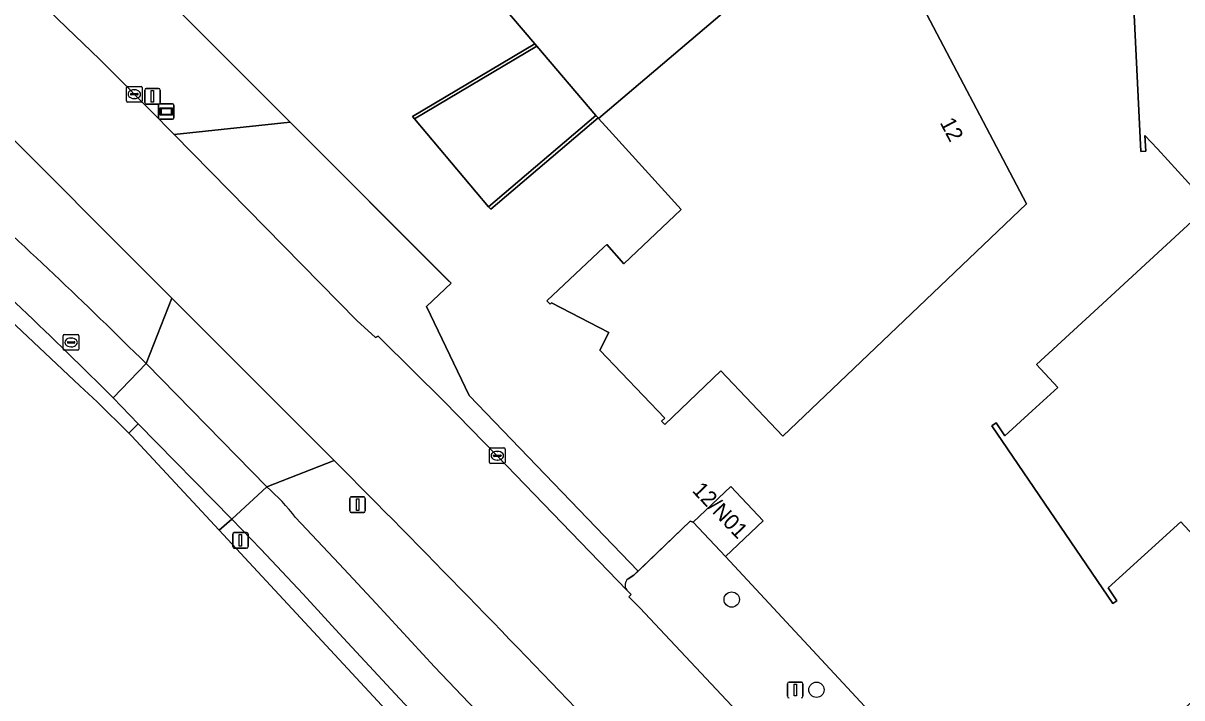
# Model space of a CAD drawing. Extents: x 156141 to 158132, y 385651 to 388333.
# Drawn here: x 156991.8 to 157065.9, y 387182.4 to 387225.5 of the extents above; entities that cross this region are included whole.
import ezdxf

# ---------------------------------------------------------------- set-up
doc = ezdxf.new("R2010")
doc.units = 0
for name, color, linetype in [('IMGEO_Berm_groen', 7, 'Continuous'), ('IMGEO_Boom', 7, 'Continuous'), ('IMGEO_Erf', 7, 'Continuous'), ('IMGEO_Fietspad_gesloten', 7, 'Continuous'), ('IMGEO_Fietspad_open', 7, 'Continuous'), ('IMGEO_Groenvoorziening', 7, 'Continuous'), ('IMGEO_Hek', 7, 'Continuous'), ('IMGEO_Kolk', 7, 'Continuous'), ('IMGEO_Lichtmast', 7, 'Continuous'), ('IMGEO_Muur', 7, 'Continuous'), ('IMGEO_Pand', 7, 'Continuous'), ('IMGEO_Pand_nummerreeks', 7, 'Continuous'), ('IMGEO_Rijbaan_lokaal_gesloten', 7, 'Continuous'), ('IMGEO_Rijbaan_lokaal_open', 7, 'Continuous'), ('IMGEO_Rioolput', 7, 'Continuous'), ('IMGEO_Wegwijzer', 7, 'Continuous')]:
    doc.layers.add(name, color=color, linetype=linetype)

msp = doc.modelspace()

# ---------------------------------------------------------------- linework, layer by layer
at = {"layer": 'IMGEO_Berm_groen'}
for points in [[(156965.011, 387230.99), (156964.564, 387230.452), (156961.521, 387232.939), (156961.968, 387233.478), (156958.815, 387236.009), (156953.758, 387240.213), (156952.456, 387238.618), (156962.253, 387231.604), (156965.736, 387229.067), (156977.276, 387219.476), (156995.449, 387202.366), (156996.546, 387201.334), (156998.572, 387199.353), (156999.182, 387199.949), (156997.574, 387201.592)], [(156999.677, 387203.787), (157001.323, 387207.973), (157000, 387209.296), (156990.371, 387218.942)], [(157011.705, 387197.589), (157007.402, 387195.905)], [(157015.869, 387182.394), (157012.017, 387186.535), (157009.711, 387189.05), (157007.02, 387191.932), (157005.158, 387193.845), (157004.351, 387193.14), (157039.884, 387154.835), (157040.992, 387155.821)], [(157009.235, 387193.956), (157012.007, 387191.001), (157014.387, 387188.458), (157018.115, 387184.42), (157026.905, 387175.201), (157034.035, 387167.898)], [(157036.705, 387191.466), (157034.641, 387193.656), (157034.448, 387193.714), (157031.114, 387190.532), (157030.835, 387190.266), (157030.47, 387190.038)], [(157047.846, 387173.887), (157048.291, 387174.308), (157050.601, 387176.491), (157036.705, 387191.466)], [(157030.388, 387189.32), (157030.673, 387189.036), (157030.526, 387188.894), (157031.238, 387188.155), (157032.174, 387187.166), (157038.405, 387180.543), (157044.624, 387173.91), (157047.141, 387173.663)]]:
    msp.add_lwpolyline(points, dxfattribs=at)
for centre, radius, start, end in [((156761.539, 386963.983), 337.958, 45.19977, 47.97908), ((156787.301, 386991.993), 296.895, 44.90806, 48.06735), ((156203.16, 386393.504), 1140.306, 42.391343, 44.841524), ((156997.872, 387185.106), 14.403, 37.91383, 48.57257), ((157030.801, 387189.637), 0.52, 129.4835, 217.4859)]:
    msp.add_arc(centre, radius, start, end, dxfattribs=at)
at = {"layer": 'IMGEO_Boom'}
for centre in [(157037.096, 387188.713), (157042.511, 387182.946)]:
    msp.add_circle(centre, 0.489, dxfattribs=at)
at = {"layer": 'IMGEO_Erf'}
for points in [[(156997.335, 387280.22), (156972.874, 387258.731), (156991.615, 387236.498), (157008.894, 387219.22), (157018.971, 387209.107), (157019.161, 387208.917), (157017.59, 387207.429), (157020.313, 387201.752), (157031.114, 387190.532), (157034.448, 387193.714), (157034.641, 387193.656), (157037.049, 387195.925), (157039.113, 387193.735), (157036.705, 387191.466), (157050.601, 387176.491), (157048.291, 387174.308), (157048.528, 387174.052), (157052.568, 387169.626), (157055.477, 387172.297), (157057.621, 387174.266), (157112.914, 387223.48), (157031.438, 387308.365)], [(157048.706, 387227.722), (157055.928, 387213.996), (157043.989, 387202.608), (157040.37, 387199.156), (157036.401, 387203.316), (157032.819, 387199.899), (157032.619, 387200.109), (157032.822, 387200.303), (157028.67, 387204.648), (157029.24, 387205.772), (157025.585, 387207.674), (157025.49, 387207.584), (157025.289, 387207.793), (157028.925, 387211.226), (157029.107, 387211.397), (157030.197, 387210.165), (157033.857, 387213.637), (157029.275, 387218.693), (157028.582, 387219.458), (157028.556, 387219.488), (157021.699, 387213.662), (157021.563, 387213.812), (157016.834, 387219.422), (157016.707, 387219.58), (157024.515, 387224.225), (156992.227, 387262.063)], [(157004.351, 387193.14), (156998.747, 387199.182), (156998.572, 387199.353), (156996.546, 387201.334), (156995.449, 387202.366), (156977.276, 387219.476), (156965.736, 387229.067), (156962.253, 387231.604), (156952.456, 387238.618), (156950.818, 387239.951)], [(157095.584, 387231.691), (157096.188, 387218.901), (157067.127, 387192.219), (157065.781, 387193.685), (157061.151, 387189.461), (157061.711, 387188.633), (157061.451, 387188.457), (157053.723, 387199.813), (157053.988, 387199.995), (157054.554, 387199.175), (157056.289, 387200.779), (157057.925, 387202.258), (157056.571, 387203.729), (157060.251, 387207.115), (157065.962, 387212.372), (157067.595, 387213.884), (157064.294, 387217.5), (157063.491, 387218.365), (157063.559, 387217.357), (157063.234, 387217.336), (157062.586, 387230.462)], [(156812.198, 386966.594), (156822.213, 386974.908), (156848.13, 386996.224), (156874.15, 387017.659), (156896.783, 387036.297), (156892.303, 387041.901), (156921.298, 387066.084), (156921.519, 387066.268), (156984.627, 387118.632), (156988.707, 387113.846), (157030.869, 387062.796), (157072.837, 387097.374), (157078.507, 387102.046), (157050.664, 387135.786), (157053.949, 387138.526), (157054.316, 387138.824), (157047.156, 387147.091), (157045.589, 387148.768), (157045.548, 387148.73), (157039.884, 387154.835), (157004.351, 387193.14)]]:
    msp.add_lwpolyline(points, dxfattribs=at)
at = {"layer": 'IMGEO_Fietspad_gesloten'}
for points in [[(156997.574, 387201.592), (156999.677, 387203.787)], [(157007.402, 387195.905), (157005.158, 387193.845), (157007.02, 387191.932), (157009.711, 387189.05), (157012.017, 387186.535), (157015.869, 387182.394), (157024.66, 387173.096), (157031.78, 387165.828)], [(157034.035, 387167.898), (157026.905, 387175.201), (157018.115, 387184.42), (157014.387, 387188.458), (157012.007, 387191.001), (157009.235, 387193.956)]]:
    msp.add_lwpolyline(points, dxfattribs=at)
for centre, radius, start, end in [((156761.539, 386963.983), 337.958, 45.19977, 47.97908), ((156787.301, 386991.993), 296.895, 44.90806, 48.06735), ((156997.872, 387185.106), 14.403, 37.91383, 48.57257)]:
    msp.add_arc(centre, radius, start, end, dxfattribs=at)
at = {"layer": 'IMGEO_Fietspad_open'}
msp.add_lwpolyline([(156999.677, 387203.787), (156997.574, 387201.592), (156999.182, 387199.949), (157005.158, 387193.845), (157007.402, 387195.905)], close=True, dxfattribs=at)
at = {"layer": 'IMGEO_Groenvoorziening'}
msp.add_lwpolyline([(156967.444, 387257.514), (156967.793, 387257.148), (156971.51, 387253.257), (156972.917, 387254.49), (156976.669, 387250.523), (156975.389, 387249.304), (156973.004, 387247.06), (156981.096, 387238.787), (156983.277, 387236.557), (156983.14, 387236.417), (156983.736, 387235.751), (156994.606, 387225.243), (156996.699, 387223.238), (156998.437, 387221.508), (156999.173, 387220.753), (157000, 387219.913), (157001.467, 387218.423), (157008.894, 387219.22), (156991.615, 387236.498), (156972.874, 387258.731)], dxfattribs=at)
at = {"layer": 'IMGEO_Hek'}
for points in [[(157008.894, 387219.22), (157019.161, 387208.917), (157017.59, 387207.429), (157020.313, 387201.752), (157031.114, 387190.532)], [(157004.351, 387193.14), (156998.747, 387199.182)], [(157034.448, 387193.714), (157030.835, 387190.266)], [(157039.884, 387154.835), (157004.351, 387193.14)]]:
    msp.add_lwpolyline(points, dxfattribs=at)
at = {"layer": 'IMGEO_Kolk'}
for p, q in [((156998.43, 387220.575), (156998.43, 387221.427)), ((156998.505, 387221.501), (156999.357, 387221.501)), ((156998.918, 387221.281), (156998.943, 387221.281)), ((156999.431, 387221.427), (156999.431, 387220.575)), ((156999.357, 387220.501), (156998.505, 387220.501)), ((156998.689, 387220.995), (156998.689, 387221.007)), ((156999.127, 387220.958), (156998.729, 387220.958)), ((156998.732, 387221.044), (156999.13, 387221.044)), ((156998.941, 387220.721), (156998.916, 387220.721)), ((156999.173, 387221.007), (156999.173, 387220.995)), ((157021.618, 387197.473), (157021.618, 387198.325)), ((157021.693, 387198.399), (157022.545, 387198.399)), ((157022.106, 387198.179), (157022.131, 387198.179)), ((157022.619, 387198.325), (157022.619, 387197.473)), ((157022.545, 387197.399), (157021.693, 387197.399)), ((157021.877, 387197.893), (157021.877, 387197.905)), ((157022.315, 387197.856), (157021.917, 387197.856)), ((157021.92, 387197.942), (157022.318, 387197.942)), ((157022.129, 387197.619), (157022.104, 387197.619)), ((157022.361, 387197.905), (157022.361, 387197.893))]:
    msp.add_line(p, q, dxfattribs=at)
for points in [[(156998.43, 387220.575), (156998.43, 387221.427)], [(156998.505, 387221.501), (156999.357, 387221.501)], [(156999.431, 387221.427), (156999.431, 387220.575)], [(156999.357, 387220.501), (156998.505, 387220.501)], [(157021.618, 387197.473), (157021.618, 387198.325)], [(157021.693, 387198.399), (157022.545, 387198.399)], [(157022.619, 387198.325), (157022.619, 387197.473)], [(157022.545, 387197.399), (157021.693, 387197.399)]]:
    msp.add_lwpolyline(points, dxfattribs=at)
for centre, radius, start, end in [((156998.507, 387221.425), 0.0765, 91.55205, 178.44795), ((156998.507, 387221.425), 0.0765, 91.55205, 178.44795), ((156999.355, 387221.425), 0.0765, 1.55205, 88.44795), ((156999.355, 387221.425), 0.0765, 1.55205, 88.44795), ((156998.507, 387220.577), 0.0765, 181.55205, 268.44795), ((156998.507, 387220.577), 0.0765, 181.55205, 268.44795), ((156998.729, 387221.004), 0.0403, 85.87752, 175.75265), ((156998.726, 387220.994), 0.0366, 178.93798, 274.71019), ((156999.13, 387221.001), 0.043, 264.86636, 352.45326), ((156999.134, 387221.006), 0.0386, 1.73085, 96.63898), ((156999.355, 387220.577), 0.0765, 271.55205, 358.44795), ((156999.355, 387220.577), 0.0765, 271.55205, 358.44795), ((157021.695, 387198.323), 0.0765, 91.55205, 178.44795), ((157021.695, 387198.323), 0.0765, 91.55205, 178.44795), ((157022.543, 387198.323), 0.0765, 1.55205, 88.44795), ((157022.543, 387198.323), 0.0765, 1.55205, 88.44795), ((157021.695, 387197.475), 0.0765, 181.55205, 268.44795), ((157021.695, 387197.475), 0.0765, 181.55205, 268.44795), ((157021.917, 387197.902), 0.0403, 85.87752, 175.75265), ((157021.914, 387197.892), 0.0366, 178.93798, 274.71019), ((157022.318, 387197.899), 0.043, 264.86636, 352.45326), ((157022.322, 387197.904), 0.0386, 1.73085, 96.63898), ((157022.543, 387197.475), 0.0765, 271.55205, 358.44795), ((157022.543, 387197.475), 0.0765, 271.55205, 358.44795)]:
    msp.add_arc(centre, radius, start, end, dxfattribs=at)
for centre, major_axis, ratio, start_param, end_param in [((156998.917, 387221.001), (-0.387, 0.002), 0.722429, 4.712389, 7.853982), ((156998.942, 387221.001), (-0.39, 0.002), 0.717154, 1.570796, 4.712389), ((157022.105, 387197.899), (-0.387, 0.002), 0.722429, 4.712389, 7.853982), ((157022.13, 387197.899), (-0.39, 0.002), 0.717154, 1.570796, 4.712389)]:
    msp.add_ellipse(centre, major_axis=major_axis, ratio=ratio, start_param=start_param, end_param=end_param, dxfattribs=at)
at = {"layer": 'IMGEO_Lichtmast'}
for p, q in [((156999.593, 387220.466), (156999.593, 387221.266)), ((156999.593, 387221.266), (156999.593, 387220.466)), ((156999.693, 387221.366), (157000.483, 387221.366)), ((157000.483, 387221.366), (156999.693, 387221.366)), ((157000.583, 387221.266), (157000.583, 387220.466)), ((157000.583, 387220.466), (157000.583, 387221.266)), ((157000.483, 387220.366), (156999.693, 387220.366)), ((156999.693, 387220.366), (157000.483, 387220.366)), ((157012.693, 387194.375), (157012.693, 387195.175)), ((157012.693, 387195.175), (157012.693, 387194.375)), ((157012.793, 387195.275), (157013.583, 387195.275)), ((157013.583, 387195.275), (157012.793, 387195.275)), ((157013.683, 387195.175), (157013.683, 387194.375)), ((157013.683, 387194.375), (157013.683, 387195.175)), ((157013.583, 387194.275), (157012.793, 387194.275)), ((157012.793, 387194.275), (157013.583, 387194.275)), ((157005.315, 387192.993), (157006.105, 387192.993)), ((157006.105, 387192.993), (157005.315, 387192.993)), ((157005.215, 387192.093), (157005.215, 387192.893)), ((157005.215, 387192.893), (157005.215, 387192.093)), ((157006.205, 387192.893), (157006.205, 387192.093)), ((157006.205, 387192.093), (157006.205, 387192.893)), ((157006.105, 387191.993), (157005.315, 387191.993)), ((157005.315, 387191.993), (157006.105, 387191.993)), ((157040.658, 387182.532), (157040.658, 387183.332)), ((157040.658, 387183.332), (157040.658, 387182.532)), ((157040.758, 387183.432), (157041.548, 387183.432)), ((157041.548, 387183.432), (157040.758, 387183.432)), ((157041.648, 387183.332), (157041.648, 387182.532)), ((157041.648, 387182.532), (157041.648, 387183.332))]:
    msp.add_line(p, q, dxfattribs=at)
for points in [[(157000.013, 387221.241), (157000.163, 387221.241), (157000.163, 387220.491), (157000.013, 387220.491), (157000.013, 387221.241)], [(157013.113, 387195.15), (157013.263, 387195.15), (157013.263, 387194.4), (157013.113, 387194.4), (157013.113, 387195.15)], [(157005.635, 387192.868), (157005.785, 387192.868), (157005.785, 387192.118), (157005.635, 387192.118), (157005.635, 387192.868)], [(157041.078, 387183.307), (157041.228, 387183.307), (157041.228, 387182.557), (157041.078, 387182.557), (157041.078, 387183.307)]]:
    msp.add_lwpolyline(points, dxfattribs=at)
for centre, start, end in [((156999.693, 387221.266), 90, 180), ((156999.693, 387221.266), 90, 180), ((157000.483, 387221.266), 0, 90), ((157000.483, 387221.266), 360, 90), ((156999.693, 387220.466), 180, 270), ((156999.693, 387220.466), 180, 270), ((157000.483, 387220.466), 270, 0), ((157000.483, 387220.466), 270, 0), ((157012.793, 387195.175), 90, 180), ((157012.793, 387195.175), 90, 180), ((157013.583, 387195.175), 0, 90), ((157013.583, 387195.175), 360, 90), ((157012.793, 387194.375), 180, 270), ((157012.793, 387194.375), 180, 270), ((157013.583, 387194.375), 270, 0), ((157013.583, 387194.375), 270, 0), ((157005.315, 387192.893), 90, 180), ((157005.315, 387192.893), 90, 180), ((157006.105, 387192.893), 0, 90), ((157006.105, 387192.893), 360, 90), ((157005.315, 387192.093), 180, 270), ((157005.315, 387192.093), 180, 270), ((157006.105, 387192.093), 270, 0), ((157006.105, 387192.093), 270, 0), ((157040.758, 387183.332), 90, 180), ((157040.758, 387183.332), 90, 180), ((157041.548, 387183.332), 0, 90), ((157041.548, 387183.332), 360, 90), ((157040.758, 387182.532), 180, 270), ((157040.758, 387182.532), 180, 270), ((157041.548, 387182.532), 270, 0), ((157041.548, 387182.532), 270, 0)]:
    msp.add_arc(centre, 0.1, start, end, dxfattribs=at)
at = {"layer": 'IMGEO_Muur'}
for points in [[(157024.648, 387224.069), (157024.515, 387224.225), (157016.707, 387219.58), (157016.834, 387219.422)], [(157028.556, 387219.488), (157028.425, 387219.642), (157021.563, 387213.812), (157021.699, 387213.662)]]:
    msp.add_lwpolyline(points, close=True, dxfattribs=at)
at = {"layer": 'IMGEO_Pand'}
for points in [[(157019.28, 387284.337), (156992.227, 387262.063), (157024.515, 387224.225), (157024.648, 387224.069), (157028.425, 387219.642), (157028.556, 387219.488), (157028.582, 387219.458), (157045.376, 387233.716)], [(157048.706, 387227.722), (157045.376, 387233.716), (157028.582, 387219.458), (157029.275, 387218.693), (157033.857, 387213.637), (157030.197, 387210.165), (157029.107, 387211.397), (157028.925, 387211.226), (157025.289, 387207.793), (157025.49, 387207.584), (157025.585, 387207.674), (157029.24, 387205.772), (157028.67, 387204.648), (157032.822, 387200.303), (157032.619, 387200.109), (157032.819, 387199.899), (157036.401, 387203.316), (157040.37, 387199.156), (157043.989, 387202.608), (157055.928, 387213.996)], [(157036.705, 387191.466), (157039.113, 387193.735), (157037.049, 387195.925), (157034.641, 387193.656)]]:
    msp.add_lwpolyline(points, close=True, dxfattribs=at)
msp.add_lwpolyline([(157062.586, 387230.462), (157063.234, 387217.336), (157063.559, 387217.357), (157063.491, 387218.365), (157064.294, 387217.5), (157067.595, 387213.884), (157065.962, 387212.372), (157060.251, 387207.115), (157056.571, 387203.729), (157057.925, 387202.258), (157056.289, 387200.779), (157054.554, 387199.175), (157053.988, 387199.995), (157053.723, 387199.813), (157061.451, 387188.457), (157061.711, 387188.633), (157061.151, 387189.461), (157065.781, 387193.685), (157067.127, 387192.219), (157096.188, 387218.901), (157095.584, 387231.691)], dxfattribs=at)
at = {"layer": 'IMGEO_Rijbaan_lokaal_gesloten'}
for points in [[(157052.393, 387165.368), (157048.511, 387169.641), (157044.624, 387173.91), (157038.405, 387180.543), (157032.174, 387187.166), (157031.238, 387188.155), (157030.526, 387188.894), (157030.673, 387189.036), (157030.388, 387189.32), (157022.114, 387197.898), (157018.716, 387201.374), (157014.65, 387205.396), (157014.508, 387205.533), (157014.332, 387205.461), (157013.15, 387206.55), (157001.467, 387218.423), (157000, 387219.913), (156999.173, 387220.753), (156998.437, 387221.508), (156996.699, 387223.238), (156994.606, 387225.243), (156983.736, 387235.751)], [(156990.371, 387218.942), (157000, 387209.296), (157001.323, 387207.973), (157010.545, 387198.754), (157011.125, 387198.172), (157011.705, 387197.589)]]:
    msp.add_lwpolyline(points, dxfattribs=at)
msp.add_lwpolyline([(157028.425, 387219.642), (157024.648, 387224.069), (157016.834, 387219.422), (157021.563, 387213.812)], close=True, dxfattribs=at)
msp.add_arc((156203.16, 386393.504), 1140.306, 42.391343, 44.841524, dxfattribs=at)
at = {"layer": 'IMGEO_Rijbaan_lokaal_open'}
for points in [[(157017.59, 387207.429), (157019.161, 387208.917), (157018.971, 387209.107), (157008.894, 387219.22), (157001.467, 387218.423), (157013.15, 387206.55), (157014.332, 387205.461), (157014.508, 387205.533), (157014.65, 387205.396), (157018.716, 387201.374), (157022.114, 387197.898), (157030.388, 387189.32)], [(157030.47, 387190.038), (157030.835, 387190.266), (157031.114, 387190.532), (157020.313, 387201.752), (157017.59, 387207.429)]]:
    msp.add_lwpolyline(points, dxfattribs=at)
for points in [[(157011.705, 387197.589), (157011.125, 387198.172), (157010.545, 387198.754), (157001.323, 387207.973), (156999.677, 387203.787), (157007.402, 387195.905)], [(156999.182, 387199.949), (156998.572, 387199.353), (156998.747, 387199.182), (157004.351, 387193.14), (157005.158, 387193.845)]]:
    msp.add_lwpolyline(points, close=True, dxfattribs=at)
msp.add_arc((157030.801, 387189.637), 0.52, 129.4835, 217.4859, dxfattribs=at)
at = {"layer": 'IMGEO_Rioolput'}
for p, q in [((156994.39, 387204.713), (156994.39, 387205.565)), ((156994.465, 387205.639), (156995.317, 387205.639)), ((156995.391, 387205.565), (156995.391, 387204.713)), ((156994.649, 387205.133), (156994.649, 387205.145)), ((156995.087, 387205.096), (156994.689, 387205.096)), ((156994.692, 387205.182), (156995.09, 387205.182)), ((156994.901, 387204.859), (156994.876, 387204.859)), ((156994.878, 387205.419), (156994.903, 387205.419)), ((156995.133, 387205.145), (156995.133, 387205.133)), ((156995.317, 387204.639), (156994.465, 387204.639))]:
    msp.add_line(p, q, dxfattribs=at)
for points in [[(156994.39, 387204.713), (156994.39, 387205.565)], [(156994.465, 387205.639), (156995.317, 387205.639)], [(156995.391, 387205.565), (156995.391, 387204.713)], [(156995.317, 387204.639), (156994.465, 387204.639)]]:
    msp.add_lwpolyline(points, dxfattribs=at)
for centre, radius, start, end in [((156994.467, 387205.563), 0.0765, 91.55205, 178.44795), ((156994.467, 387205.563), 0.0765, 91.55205, 178.44795), ((156995.315, 387205.563), 0.0765, 1.55205, 88.44795), ((156995.315, 387205.563), 0.0765, 1.55205, 88.44795), ((156994.689, 387205.142), 0.0403, 85.87752, 175.75265), ((156994.686, 387205.132), 0.0366, 178.93798, 274.71019), ((156995.09, 387205.139), 0.043, 264.86636, 352.45326), ((156995.094, 387205.144), 0.0386, 1.73085, 96.63898), ((156994.467, 387204.715), 0.0765, 181.55205, 268.44795), ((156994.467, 387204.715), 0.0765, 181.55205, 268.44795), ((156995.315, 387204.715), 0.0765, 271.55205, 358.44795), ((156995.315, 387204.715), 0.0765, 271.55205, 358.44795)]:
    msp.add_arc(centre, radius, start, end, dxfattribs=at)
for centre, major_axis, ratio, start_param, end_param in [((156994.877, 387205.139), (-0.387, 0.002), 0.722429, 4.712389, 7.853982), ((156994.902, 387205.139), (-0.39, 0.002), 0.717154, 1.570796, 4.712389)]:
    msp.add_ellipse(centre, major_axis=major_axis, ratio=ratio, start_param=start_param, end_param=end_param, dxfattribs=at)
at = {"layer": 'IMGEO_Wegwijzer'}
for p, q in [((157000.57, 387220.395), (157001.36, 387220.395)), ((157001.36, 387220.395), (157000.57, 387220.395)), ((157000.47, 387219.495), (157000.47, 387220.295)), ((157000.47, 387220.295), (157000.47, 387219.495)), ((157001.46, 387220.295), (157001.46, 387219.495)), ((157001.46, 387219.495), (157001.46, 387220.295)), ((157001.36, 387219.395), (157000.57, 387219.395)), ((157000.57, 387219.395), (157001.36, 387219.395))]:
    msp.add_line(p, q, dxfattribs=at)
for points in [[(157000.571, 387220.127), (157001.359, 387220.127), (157001.359, 387219.663), (157000.571, 387219.663), (157000.571, 387220.127)], [(157000.636, 387220.062), (157000.636, 387219.728), (157001.294, 387219.728), (157001.294, 387220.062), (157000.636, 387220.062)]]:
    msp.add_lwpolyline(points, dxfattribs=at)
for centre, start, end in [((157000.57, 387220.295), 90, 180), ((157000.57, 387220.295), 90, 180), ((157001.36, 387220.295), 0, 90), ((157001.36, 387220.295), 360, 90), ((157000.57, 387219.495), 180, 270), ((157000.57, 387219.495), 180, 270), ((157001.36, 387219.495), 270, 0), ((157001.36, 387219.495), 270, 0)]:
    msp.add_arc(centre, 0.1, start, end, dxfattribs=at)

# ---------------------------------------------------------------- texts
at = {"layer": 'IMGEO_Pand_nummerreeks'}
for s, rotation, p in [('12', 297.55333, (157050.373, 387219.19)), ('12/N01', 313.70394, (157034.515, 387195.639))]:
    msp.add_text(s, height=1, rotation=rotation, dxfattribs=at).set_placement(p)

doc.saveas('drawing.dxf')
